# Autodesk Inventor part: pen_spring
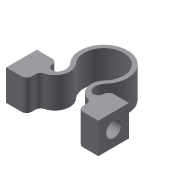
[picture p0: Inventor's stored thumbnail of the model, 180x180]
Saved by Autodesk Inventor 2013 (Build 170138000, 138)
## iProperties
Created: 2013-11
Part Number: pen_spring
Material: Generic
Document SubType Name: Modeling
Designer: Jonas
Density: 1 g/cm^3
Author: Jonas
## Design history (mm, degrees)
sketch "Sketch1"
  geometry: L1 (5, 3)-(9, 3); L2 (9, 3)-(9, -3); L3 (9, -3)-(5, -3); L4 (5, -3)-(5, 3); 2 further points
  constraints: 8 end point, 2 parallel, 1 horizontal, 1 horizontal alignment, 1 midpoint, 1 perpendicular
  dimensions: "d0" = 4 distance of L1.start L1.end; "d2" = 6 distance of L1.end L2.end; "d3" = 9 distance from line of L2 point (0, 0)
extrude "Extrusion1" new body sketch "Sketch1" distance "d4" = 6; taper "d5" = 0 deg
sketch "Sketch2"
  geometry: L1 (9, 3)-(5, 3) reference; L2 (5, 3)-(5, -3) reference; L3 (5, -3)-(9, -3) reference; L4 (9, -3)-(9, 3) reference; L5 (0, 11.756)-(0, 10.956); L6 (5, -0.4)-(5, 0.4); A1 r 3.864 centre (0, 7.092) between (2.85, 4.483) and (0, 10.956); A2 r 2.915 centre (5, 2.515) between (2.85, 4.483) and (5, -0.4); A3 r 2.115 centre (5, 2.515) between (3.44, 3.943) and (5, 0.4); A4 r 4.664 centre (0, 7.092) between (3.44, 3.943) and (0, 11.756); 2 further points
  constraints: 8 point on circle, 4 centre point, 4 end point, 2 midpoint, 2 parallel, 2 point on line, 2 vertical alignment, 1 tangent, 1 other
  dimensions: "d6" = 0.8 radial gap between concentric circles of A4 A1; "d15" = 0.8 distance of L6.start L6.end
extrude "Extrusion2" join sketch "Sketch2" stored distance "d8" = 4; taper "d9" = 0 deg
fillet "Fillet1" dims "d10" = 1
sketch "Sketch3"
  geometry: L1 (0, 6)-(0, 0) reference; L2 (0, 0)-(-6, 0) reference; C1 r 1.45 at (-3, 3); 3 further points
  constraints: 2 midpoint, 1 centre point, 1 horizontal alignment, 1 vertical alignment
  dimensions: "d11" = 2.9 diameter of C1
extrude "Extrusion3" cut sketch "Sketch3" distance "d12" = 3; taper "d13" = 0 deg
mirror "Mirror1"
body "Solid1"
node "Projected Loop1"
